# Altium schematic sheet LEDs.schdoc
size 169 x 182 mm
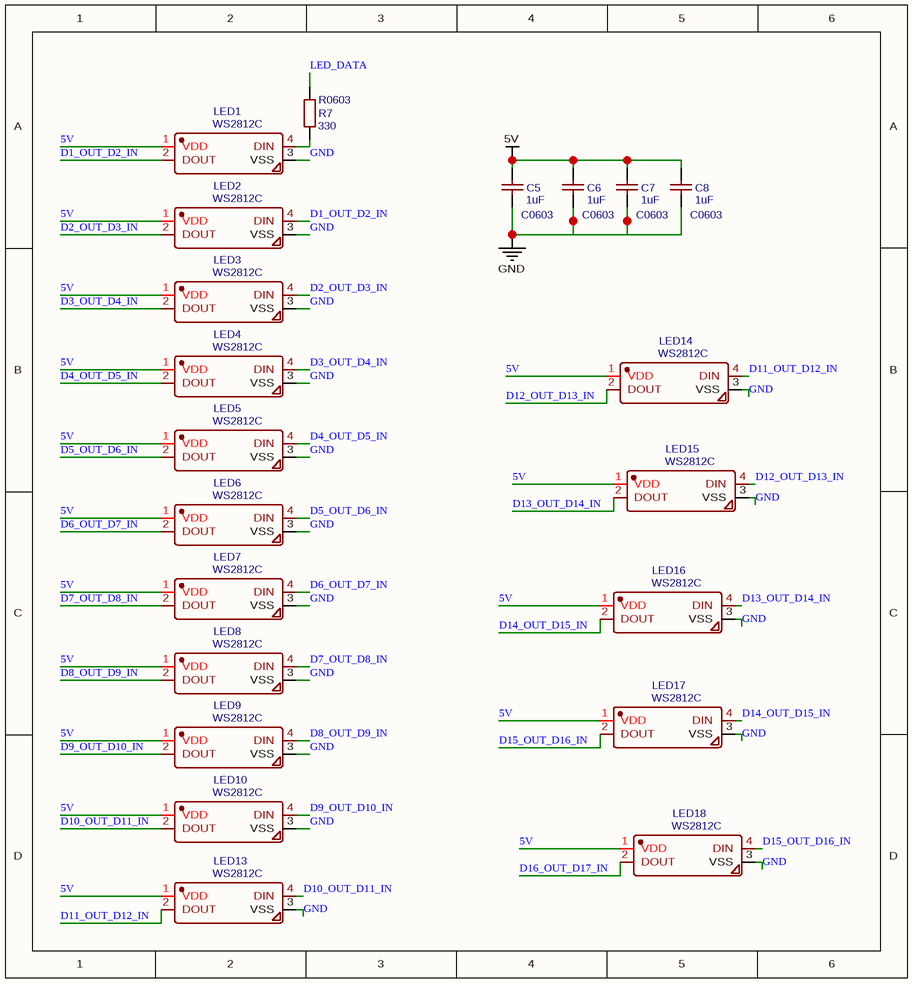
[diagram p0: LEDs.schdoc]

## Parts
C5  1uF  [C0603]
C6  1uF  [C0603]
C7  1uF  [C0603]
C8  1uF  [C0603]
LED1  WS2812C  [LED-SMD_4P-L5.0-W5.0-BL]
LED2  WS2812C  [LED-SMD_4P-L5.0-W5.0-BL]
LED3  WS2812C  [LED-SMD_4P-L5.0-W5.0-BL]
LED4  WS2812C  [LED-SMD_4P-L5.0-W5.0-BL]
LED5  WS2812C  [LED-SMD_4P-L5.0-W5.0-BL]
LED6  WS2812C  [LED-SMD_4P-L5.0-W5.0-BL]
LED7  WS2812C  [LED-SMD_4P-L5.0-W5.0-BL]
LED8  WS2812C  [LED-SMD_4P-L5.0-W5.0-BL]
LED9  WS2812C  [LED-SMD_4P-L5.0-W5.0-BL]
LED10  WS2812C  [LED-SMD_4P-L5.0-W5.0-BL]
LED13  WS2812C  [LED-SMD_4P-L5.0-W5.0-BL]
LED14  WS2812C  [LED-SMD_4P-L5.0-W5.0-BL]
LED15  WS2812C  [LED-SMD_4P-L5.0-W5.0-BL]
LED16  WS2812C  [LED-SMD_4P-L5.0-W5.0-BL]
LED17  WS2812C  [LED-SMD_4P-L5.0-W5.0-BL]
LED18  WS2812C  [LED-SMD_4P-L5.0-W5.0-BL]
R7  330  [R0603]

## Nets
5V: C5.2 C6.2 C7.2 C8.2 LED1.1(VDD) LED2.1(VDD) LED3.1(VDD) LED4.1(VDD) LED5.1(VDD) LED6.1(VDD) LED7.1(VDD) LED8.1(VDD) LED9.1(VDD) LED10.1(VDD) LED13.1(VDD) LED14.1(VDD) LED15.1(VDD) LED16.1(VDD) LED17.1(VDD) LED18.1(VDD)
GND: C5.1 C6.1 C7.1 C8.1 LED1.3(VSS) LED2.3(VSS) LED3.3(VSS) LED4.3(VSS) LED5.3(VSS) LED6.3(VSS) LED7.3(VSS) LED8.3(VSS) LED9.3(VSS) LED10.3(VSS) LED13.3(VSS) LED14.3(VSS) LED15.3(VSS) LED16.3(VSS) LED17.3(VSS) LED18.3(VSS)
D1_OUT_D2_IN: LED1.2(DOUT) LED2.4(DIN)
D2_OUT_D3_IN: LED2.2(DOUT) LED3.4(DIN)
D3_OUT_D4_IN: LED3.2(DOUT) LED4.4(DIN)
D4_OUT_D5_IN: LED4.2(DOUT) LED5.4(DIN)
D5_OUT_D6_IN: LED5.2(DOUT) LED6.4(DIN)
D6_OUT_D7_IN: LED6.2(DOUT) LED7.4(DIN)
D7_OUT_D8_IN: LED7.2(DOUT) LED8.4(DIN)
D8_OUT_D9_IN: LED8.2(DOUT) LED9.4(DIN)
D9_OUT_D10_IN: LED9.2(DOUT) LED10.4(DIN)
D10_OUT_D11_IN: LED10.2(DOUT) LED13.4(DIN)
D11_OUT_D12_IN: LED13.2(DOUT) LED14.4(DIN)
D12_OUT_D13_IN: LED14.2(DOUT) LED15.4(DIN)
D13_OUT_D14_IN: LED15.2(DOUT) LED16.4(DIN)
D14_OUT_D15_IN: LED16.2(DOUT) LED17.4(DIN)
D15_OUT_D16_IN: LED17.2(DOUT) LED18.4(DIN)
D16_OUT_D17_IN: LED18.2(DOUT)
LED_DATA: R7.2
NetLED1_4: LED1.4(DIN) R7.1

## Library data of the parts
C5-C8 = 1uF: BOM_Manufacturer Part: CL10A105KB8NNNC; BOM_Manufacturer: SAMSUNG; nameAlias: Capacitance; SMT Type: Basic; Package Display: Yes
LED1-LED10 LED13-LED18 = WS2812C: BOM_Manufacturer: Worldsemi; Contributor: LCSC
R7 = 330: BOM_Manufacturer: UniOhm; BOM_Manufacturer Part: 0603WAF3300T5E; nameAlias: Resistance (Ohms); SMT Type: Basic; Package Display: Yes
